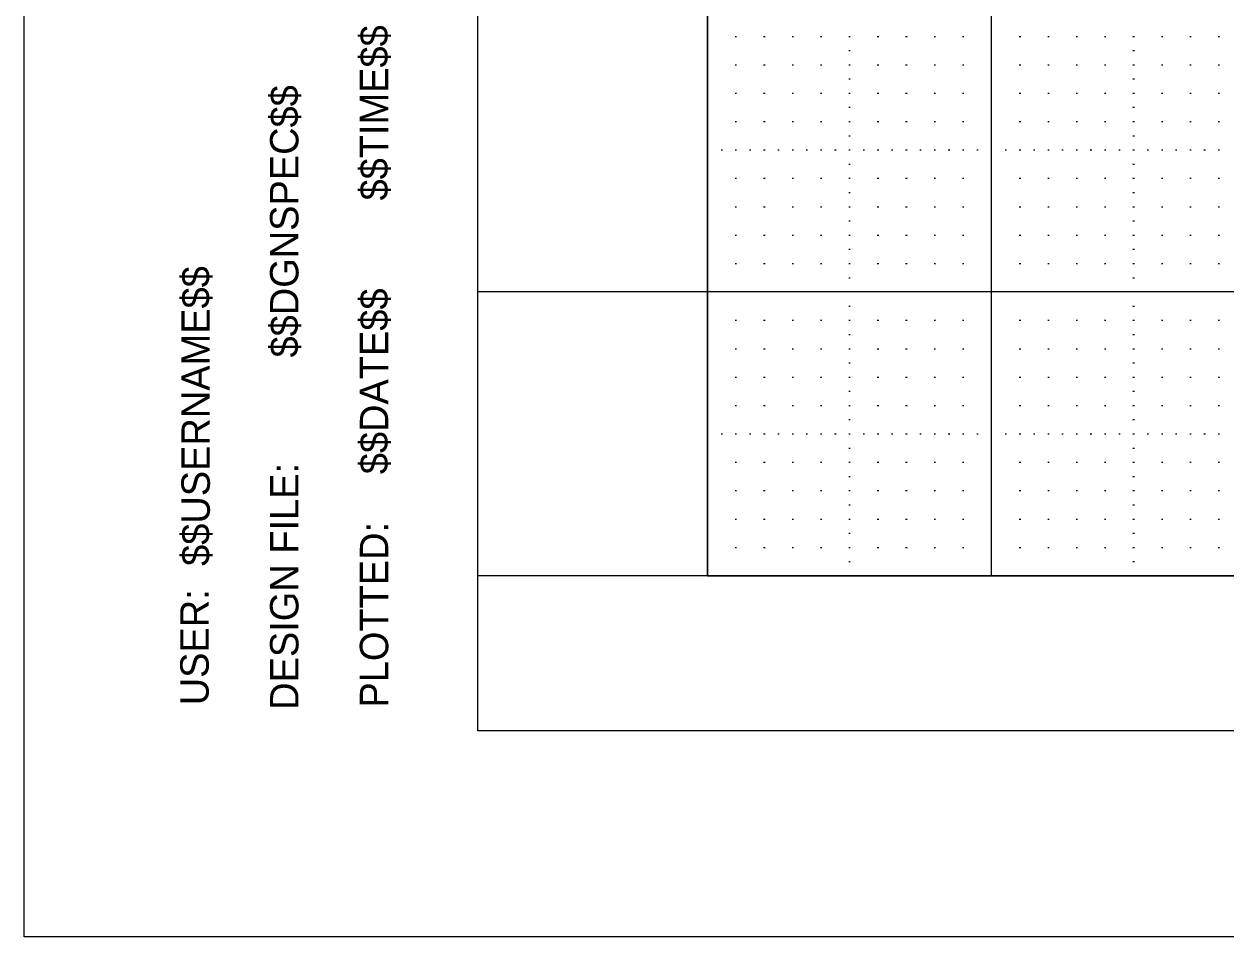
# Model space of a CAD drawing. Extents: x -1.6 to 32.4, y -1.9 to 21.6.
# Drawn here: x -1.598 to 2.633, y -0.727 to 2.488 of the extents above; entities that cross this region are included whole.
import ezdxf

# ---------------------------------------------------------------- set-up
doc = ezdxf.new("R2010")
doc.units = 0
for name, color, linetype in [('Level 1', 7, 'Continuous'), ('Level 4', 7, 'Continuous'), ('Level 5', 7, 'Continuous'), ('Level 61', 7, 'Continuous'), ('Level 63', 7, 'Continuous')]:
    doc.layers.add(name, color=color, linetype=linetype)

msp = doc.modelspace()

# ---------------------------------------------------------------- linework, layer by layer
at = {"layer": 'Level 1'}
for p, q in [((-0.001, -0.001), (-0.001, 20.545)), ((31.617, -0.001), (-0.001, -0.001))]:
    msp.add_line(p, q, dxfattribs=at)
at = {"layer": 'Level 4'}
for p, q in [((0.808, 0.545), (0.808, 20.545)), ((1.808, 0.545), (1.808, 20.545)), ((31.617, 1.545), (-0.001, 1.545)), ((31.617, 0.545), (-0.001, 0.545))]:
    msp.add_line(p, q, dxfattribs=at)
at = {"layer": 'Level 5'}
for p, q in [((0.9055, 2.445), (0.9105, 2.445)), ((1.0055, 2.445), (1.0105, 2.445)), ((1.1055, 2.445), (1.1105, 2.445)), ((1.2055, 2.445), (1.2105, 2.445)), ((1.3055, 2.445), (1.3105, 2.445)), ((1.4055, 2.445), (1.4105, 2.445)), ((1.5055, 2.445), (1.5105, 2.445)), ((1.6055, 2.445), (1.6105, 2.445)), ((1.7055, 2.445), (1.7105, 2.445)), ((1.9055, 2.445), (1.9105, 2.445)), ((2.0055, 2.445), (2.0105, 2.445)), ((2.1055, 2.445), (2.1105, 2.445)), ((2.2055, 2.445), (2.2105, 2.445)), ((2.3055, 2.445), (2.3105, 2.445)), ((2.4055, 2.445), (2.4105, 2.445)), ((2.5055, 2.445), (2.5105, 2.445)), ((2.6055, 2.445), (2.6105, 2.445)), ((1.3055, 2.395), (1.3105, 2.395)), ((2.3055, 2.395), (2.3105, 2.395)), ((0.9055, 2.345), (0.9105, 2.345)), ((1.0055, 2.345), (1.0105, 2.345)), ((1.1055, 2.345), (1.1105, 2.345)), ((1.2055, 2.345), (1.2105, 2.345)), ((1.3055, 2.345), (1.3105, 2.345)), ((1.4055, 2.345), (1.4105, 2.345)), ((1.5055, 2.345), (1.5105, 2.345)), ((1.6055, 2.345), (1.6105, 2.345)), ((1.7055, 2.345), (1.7105, 2.345)), ((1.9055, 2.345), (1.9105, 2.345)), ((2.0055, 2.345), (2.0105, 2.345)), ((2.1055, 2.345), (2.1105, 2.345)), ((2.2055, 2.345), (2.2105, 2.345)), ((2.3055, 2.345), (2.3105, 2.345)), ((2.4055, 2.345), (2.4105, 2.345)), ((2.5055, 2.345), (2.5105, 2.345)), ((2.6055, 2.345), (2.6105, 2.345)), ((1.3055, 2.295), (1.3105, 2.295)), ((2.3055, 2.295), (2.3105, 2.295)), ((0.9055, 2.245), (0.9105, 2.245)), ((1.0055, 2.245), (1.0105, 2.245)), ((1.1055, 2.245), (1.1105, 2.245)), ((1.2055, 2.245), (1.2105, 2.245)), ((1.3055, 2.245), (1.3105, 2.245)), ((1.4055, 2.245), (1.4105, 2.245)), ((1.5055, 2.245), (1.5105, 2.245)), ((1.6055, 2.245), (1.6105, 2.245)), ((1.7055, 2.245), (1.7105, 2.245)), ((1.9055, 2.245), (1.9105, 2.245)), ((2.0055, 2.245), (2.0105, 2.245)), ((2.1055, 2.245), (2.1105, 2.245)), ((2.2055, 2.245), (2.2105, 2.245)), ((2.3055, 2.245), (2.3105, 2.245)), ((2.4055, 2.245), (2.4105, 2.245)), ((2.5055, 2.245), (2.5105, 2.245)), ((2.6055, 2.245), (2.6105, 2.245)), ((1.3055, 2.195), (1.3105, 2.195)), ((2.3055, 2.195), (2.3105, 2.195)), ((0.9055, 2.145), (0.9105, 2.145)), ((1.0055, 2.145), (1.0105, 2.145)), ((1.1055, 2.145), (1.1105, 2.145)), ((1.2055, 2.145), (1.2105, 2.145)), ((1.3055, 2.145), (1.3105, 2.145)), ((1.4055, 2.145), (1.4105, 2.145)), ((1.5055, 2.145), (1.5105, 2.145)), ((1.6055, 2.145), (1.6105, 2.145)), ((1.7055, 2.145), (1.7105, 2.145)), ((1.9055, 2.145), (1.9105, 2.145)), ((2.0055, 2.145), (2.0105, 2.145)), ((2.1055, 2.145), (2.1105, 2.145)), ((2.2055, 2.145), (2.2105, 2.145)), ((2.3055, 2.145), (2.3105, 2.145)), ((2.4055, 2.145), (2.4105, 2.145)), ((2.5055, 2.145), (2.5105, 2.145)), ((2.6055, 2.145), (2.6105, 2.145)), ((1.3055, 2.095), (1.3105, 2.095)), ((2.3055, 2.095), (2.3105, 2.095)), ((0.8555, 2.045), (0.8605, 2.045)), ((0.9055, 2.045), (0.9105, 2.045)), ((0.9555, 2.045), (0.9605, 2.045)), ((1.0055, 2.045), (1.0105, 2.045)), ((1.0555, 2.045), (1.0605, 2.045)), ((1.1055, 2.045), (1.1105, 2.045)), ((1.1555, 2.045), (1.1605, 2.045)), ((1.2055, 2.045), (1.2105, 2.045)), ((1.2555, 2.045), (1.2605, 2.045)), ((1.3055, 2.045), (1.3105, 2.045)), ((1.3555, 2.045), (1.3605, 2.045)), ((1.4055, 2.045), (1.4105, 2.045)), ((1.4555, 2.045), (1.4605, 2.045)), ((1.5055, 2.045), (1.5105, 2.045)), ((1.5555, 2.045), (1.5605, 2.045)), ((1.6055, 2.045), (1.6105, 2.045)), ((1.6555, 2.045), (1.6605, 2.045)), ((1.7055, 2.045), (1.7105, 2.045)), ((1.7555, 2.045), (1.7605, 2.045)), ((1.8555, 2.045), (1.8605, 2.045)), ((1.9055, 2.045), (1.9105, 2.045)), ((1.9555, 2.045), (1.9605, 2.045)), ((2.0055, 2.045), (2.0105, 2.045)), ((2.0555, 2.045), (2.0605, 2.045)), ((2.1055, 2.045), (2.1105, 2.045)), ((2.1555, 2.045), (2.1605, 2.045)), ((2.2055, 2.045), (2.2105, 2.045)), ((2.2555, 2.045), (2.2605, 2.045)), ((2.3055, 2.045), (2.3105, 2.045)), ((2.3555, 2.045), (2.3605, 2.045)), ((2.4055, 2.045), (2.4105, 2.045)), ((2.4555, 2.045), (2.4605, 2.045)), ((2.5055, 2.045), (2.5105, 2.045)), ((2.5555, 2.045), (2.5605, 2.045)), ((2.6055, 2.045), (2.6105, 2.045)), ((1.3055, 1.995), (1.3105, 1.995)), ((2.3055, 1.995), (2.3105, 1.995)), ((0.9055, 1.945), (0.9105, 1.945)), ((1.0055, 1.945), (1.0105, 1.945)), ((1.1055, 1.945), (1.1105, 1.945)), ((1.2055, 1.945), (1.2105, 1.945)), ((1.3055, 1.945), (1.3105, 1.945)), ((1.4055, 1.945), (1.4105, 1.945)), ((1.5055, 1.945), (1.5105, 1.945)), ((1.6055, 1.945), (1.6105, 1.945)), ((1.7055, 1.945), (1.7105, 1.945)), ((1.9055, 1.945), (1.9105, 1.945)), ((2.0055, 1.945), (2.0105, 1.945)), ((2.1055, 1.945), (2.1105, 1.945)), ((2.2055, 1.945), (2.2105, 1.945)), ((2.3055, 1.945), (2.3105, 1.945)), ((2.4055, 1.945), (2.4105, 1.945)), ((2.5055, 1.945), (2.5105, 1.945)), ((2.6055, 1.945), (2.6105, 1.945)), ((1.3055, 1.895), (1.3105, 1.895)), ((2.3055, 1.895), (2.3105, 1.895)), ((0.9055, 1.845), (0.9105, 1.845)), ((1.0055, 1.845), (1.0105, 1.845)), ((1.1055, 1.845), (1.1105, 1.845)), ((1.2055, 1.845), (1.2105, 1.845)), ((1.3055, 1.845), (1.3105, 1.845)), ((1.4055, 1.845), (1.4105, 1.845)), ((1.5055, 1.845), (1.5105, 1.845)), ((1.6055, 1.845), (1.6105, 1.845)), ((1.7055, 1.845), (1.7105, 1.845)), ((1.9055, 1.845), (1.9105, 1.845)), ((2.0055, 1.845), (2.0105, 1.845)), ((2.1055, 1.845), (2.1105, 1.845)), ((2.2055, 1.845), (2.2105, 1.845)), ((2.3055, 1.845), (2.3105, 1.845)), ((2.4055, 1.845), (2.4105, 1.845)), ((2.5055, 1.845), (2.5105, 1.845)), ((2.6055, 1.845), (2.6105, 1.845)), ((1.3055, 1.795), (1.3105, 1.795)), ((2.3055, 1.795), (2.3105, 1.795)), ((0.9055, 1.745), (0.9105, 1.745)), ((1.0055, 1.745), (1.0105, 1.745)), ((1.1055, 1.745), (1.1105, 1.745)), ((1.2055, 1.745), (1.2105, 1.745)), ((1.3055, 1.745), (1.3105, 1.745)), ((1.4055, 1.745), (1.4105, 1.745)), ((1.5055, 1.745), (1.5105, 1.745)), ((1.6055, 1.745), (1.6105, 1.745)), ((1.7055, 1.745), (1.7105, 1.745)), ((1.9055, 1.745), (1.9105, 1.745)), ((2.0055, 1.745), (2.0105, 1.745)), ((2.1055, 1.745), (2.1105, 1.745)), ((2.2055, 1.745), (2.2105, 1.745)), ((2.3055, 1.745), (2.3105, 1.745)), ((2.4055, 1.745), (2.4105, 1.745)), ((2.5055, 1.745), (2.5105, 1.745)), ((2.6055, 1.745), (2.6105, 1.745)), ((1.3055, 1.695), (1.3105, 1.695)), ((2.3055, 1.695), (2.3105, 1.695)), ((0.9055, 1.645), (0.9105, 1.645)), ((1.0055, 1.645), (1.0105, 1.645)), ((1.1055, 1.645), (1.1105, 1.645)), ((1.2055, 1.645), (1.2105, 1.645)), ((1.3055, 1.645), (1.3105, 1.645)), ((1.4055, 1.645), (1.4105, 1.645)), ((1.5055, 1.645), (1.5105, 1.645)), ((1.6055, 1.645), (1.6105, 1.645)), ((1.7055, 1.645), (1.7105, 1.645)), ((1.9055, 1.645), (1.9105, 1.645)), ((2.0055, 1.645), (2.0105, 1.645)), ((2.1055, 1.645), (2.1105, 1.645)), ((2.2055, 1.645), (2.2105, 1.645)), ((2.3055, 1.645), (2.3105, 1.645)), ((2.4055, 1.645), (2.4105, 1.645)), ((2.5055, 1.645), (2.5105, 1.645)), ((2.6055, 1.645), (2.6105, 1.645)), ((1.3055, 1.595), (1.3105, 1.595)), ((2.3055, 1.595), (2.3105, 1.595)), ((1.3055, 1.495), (1.3105, 1.495)), ((2.3055, 1.495), (2.3105, 1.495)), ((0.9055, 1.445), (0.9105, 1.445)), ((1.0055, 1.445), (1.0105, 1.445)), ((1.1055, 1.445), (1.1105, 1.445)), ((1.2055, 1.445), (1.2105, 1.445)), ((1.3055, 1.445), (1.3105, 1.445)), ((1.4055, 1.445), (1.4105, 1.445)), ((1.5055, 1.445), (1.5105, 1.445)), ((1.6055, 1.445), (1.6105, 1.445)), ((1.7055, 1.445), (1.7105, 1.445)), ((1.9055, 1.445), (1.9105, 1.445)), ((2.0055, 1.445), (2.0105, 1.445)), ((2.1055, 1.445), (2.1105, 1.445)), ((2.2055, 1.445), (2.2105, 1.445)), ((2.3055, 1.445), (2.3105, 1.445)), ((2.4055, 1.445), (2.4105, 1.445)), ((2.5055, 1.445), (2.5105, 1.445)), ((2.6055, 1.445), (2.6105, 1.445)), ((1.3055, 1.395), (1.3105, 1.395)), ((2.3055, 1.395), (2.3105, 1.395)), ((0.9055, 1.345), (0.9105, 1.345)), ((1.0055, 1.345), (1.0105, 1.345)), ((1.1055, 1.345), (1.1105, 1.345)), ((1.2055, 1.345), (1.2105, 1.345)), ((1.3055, 1.345), (1.3105, 1.345)), ((1.4055, 1.345), (1.4105, 1.345)), ((1.5055, 1.345), (1.5105, 1.345)), ((1.6055, 1.345), (1.6105, 1.345)), ((1.7055, 1.345), (1.7105, 1.345)), ((1.9055, 1.345), (1.9105, 1.345)), ((2.0055, 1.345), (2.0105, 1.345)), ((2.1055, 1.345), (2.1105, 1.345)), ((2.2055, 1.345), (2.2105, 1.345)), ((2.3055, 1.345), (2.3105, 1.345)), ((2.4055, 1.345), (2.4105, 1.345)), ((2.5055, 1.345), (2.5105, 1.345)), ((2.6055, 1.345), (2.6105, 1.345)), ((1.3055, 1.295), (1.3105, 1.295)), ((2.3055, 1.295), (2.3105, 1.295)), ((0.9055, 1.245), (0.9105, 1.245)), ((1.0055, 1.245), (1.0105, 1.245)), ((1.1055, 1.245), (1.1105, 1.245)), ((1.2055, 1.245), (1.2105, 1.245)), ((1.3055, 1.245), (1.3105, 1.245)), ((1.4055, 1.245), (1.4105, 1.245)), ((1.5055, 1.245), (1.5105, 1.245)), ((1.6055, 1.245), (1.6105, 1.245)), ((1.7055, 1.245), (1.7105, 1.245)), ((1.9055, 1.245), (1.9105, 1.245)), ((2.0055, 1.245), (2.0105, 1.245)), ((2.1055, 1.245), (2.1105, 1.245)), ((2.2055, 1.245), (2.2105, 1.245)), ((2.3055, 1.245), (2.3105, 1.245)), ((2.4055, 1.245), (2.4105, 1.245)), ((2.5055, 1.245), (2.5105, 1.245)), ((2.6055, 1.245), (2.6105, 1.245)), ((1.3055, 1.195), (1.3105, 1.195)), ((2.3055, 1.195), (2.3105, 1.195)), ((0.9055, 1.145), (0.9105, 1.145)), ((1.0055, 1.145), (1.0105, 1.145)), ((1.1055, 1.145), (1.1105, 1.145)), ((1.2055, 1.145), (1.2105, 1.145)), ((1.3055, 1.145), (1.3105, 1.145)), ((1.4055, 1.145), (1.4105, 1.145)), ((1.5055, 1.145), (1.5105, 1.145)), ((1.6055, 1.145), (1.6105, 1.145)), ((1.7055, 1.145), (1.7105, 1.145)), ((1.9055, 1.145), (1.9105, 1.145)), ((2.0055, 1.145), (2.0105, 1.145)), ((2.1055, 1.145), (2.1105, 1.145)), ((2.2055, 1.145), (2.2105, 1.145)), ((2.3055, 1.145), (2.3105, 1.145)), ((2.4055, 1.145), (2.4105, 1.145)), ((2.5055, 1.145), (2.5105, 1.145)), ((2.6055, 1.145), (2.6105, 1.145)), ((1.3055, 1.095), (1.3105, 1.095)), ((2.3055, 1.095), (2.3105, 1.095)), ((0.8555, 1.045), (0.8605, 1.045)), ((0.9055, 1.045), (0.9105, 1.045)), ((0.9555, 1.045), (0.9605, 1.045)), ((1.0055, 1.045), (1.0105, 1.045)), ((1.0555, 1.045), (1.0605, 1.045)), ((1.1055, 1.045), (1.1105, 1.045)), ((1.1555, 1.045), (1.1605, 1.045)), ((1.2055, 1.045), (1.2105, 1.045)), ((1.2555, 1.045), (1.2605, 1.045)), ((1.3055, 1.045), (1.3105, 1.045)), ((1.3555, 1.045), (1.3605, 1.045)), ((1.4055, 1.045), (1.4105, 1.045)), ((1.4555, 1.045), (1.4605, 1.045)), ((1.5055, 1.045), (1.5105, 1.045)), ((1.5555, 1.045), (1.5605, 1.045)), ((1.6055, 1.045), (1.6105, 1.045)), ((1.6555, 1.045), (1.6605, 1.045)), ((1.7055, 1.045), (1.7105, 1.045)), ((1.7555, 1.045), (1.7605, 1.045)), ((1.8555, 1.045), (1.8605, 1.045)), ((1.9055, 1.045), (1.9105, 1.045)), ((1.9555, 1.045), (1.9605, 1.045)), ((2.0055, 1.045), (2.0105, 1.045)), ((2.0555, 1.045), (2.0605, 1.045)), ((2.1055, 1.045), (2.1105, 1.045)), ((2.1555, 1.045), (2.1605, 1.045)), ((2.2055, 1.045), (2.2105, 1.045)), ((2.2555, 1.045), (2.2605, 1.045)), ((2.3055, 1.045), (2.3105, 1.045)), ((2.3555, 1.045), (2.3605, 1.045)), ((2.4055, 1.045), (2.4105, 1.045)), ((2.4555, 1.045), (2.4605, 1.045)), ((2.5055, 1.045), (2.5105, 1.045)), ((2.5555, 1.045), (2.5605, 1.045)), ((2.6055, 1.045), (2.6105, 1.045)), ((1.3055, 0.995), (1.3105, 0.995)), ((2.3055, 0.995), (2.3105, 0.995)), ((0.9055, 0.945), (0.9105, 0.945)), ((1.0055, 0.945), (1.0105, 0.945)), ((1.1055, 0.945), (1.1105, 0.945)), ((1.2055, 0.945), (1.2105, 0.945)), ((1.3055, 0.945), (1.3105, 0.945)), ((1.4055, 0.945), (1.4105, 0.945)), ((1.5055, 0.945), (1.5105, 0.945)), ((1.6055, 0.945), (1.6105, 0.945)), ((1.7055, 0.945), (1.7105, 0.945)), ((1.9055, 0.945), (1.9105, 0.945)), ((2.0055, 0.945), (2.0105, 0.945)), ((2.1055, 0.945), (2.1105, 0.945)), ((2.2055, 0.945), (2.2105, 0.945)), ((2.3055, 0.945), (2.3105, 0.945)), ((2.4055, 0.945), (2.4105, 0.945)), ((2.5055, 0.945), (2.5105, 0.945)), ((2.6055, 0.945), (2.6105, 0.945)), ((1.3055, 0.895), (1.3105, 0.895)), ((2.3055, 0.895), (2.3105, 0.895)), ((0.9055, 0.845), (0.9105, 0.845)), ((1.0055, 0.845), (1.0105, 0.845)), ((1.1055, 0.845), (1.1105, 0.845)), ((1.2055, 0.845), (1.2105, 0.845)), ((1.3055, 0.845), (1.3105, 0.845)), ((1.4055, 0.845), (1.4105, 0.845)), ((1.5055, 0.845), (1.5105, 0.845)), ((1.6055, 0.845), (1.6105, 0.845)), ((1.7055, 0.845), (1.7105, 0.845)), ((1.9055, 0.845), (1.9105, 0.845)), ((2.0055, 0.845), (2.0105, 0.845)), ((2.1055, 0.845), (2.1105, 0.845)), ((2.2055, 0.845), (2.2105, 0.845)), ((2.3055, 0.845), (2.3105, 0.845)), ((2.4055, 0.845), (2.4105, 0.845)), ((2.5055, 0.845), (2.5105, 0.845)), ((2.6055, 0.845), (2.6105, 0.845)), ((1.3055, 0.795), (1.3105, 0.795)), ((2.3055, 0.795), (2.3105, 0.795)), ((0.9055, 0.745), (0.9105, 0.745)), ((1.0055, 0.745), (1.0105, 0.745)), ((1.1055, 0.745), (1.1105, 0.745)), ((1.2055, 0.745), (1.2105, 0.745)), ((1.3055, 0.745), (1.3105, 0.745)), ((1.4055, 0.745), (1.4105, 0.745)), ((1.5055, 0.745), (1.5105, 0.745)), ((1.6055, 0.745), (1.6105, 0.745)), ((1.7055, 0.745), (1.7105, 0.745)), ((1.9055, 0.745), (1.9105, 0.745)), ((2.0055, 0.745), (2.0105, 0.745)), ((2.1055, 0.745), (2.1105, 0.745)), ((2.2055, 0.745), (2.2105, 0.745)), ((2.3055, 0.745), (2.3105, 0.745)), ((2.4055, 0.745), (2.4105, 0.745)), ((2.5055, 0.745), (2.5105, 0.745)), ((2.6055, 0.745), (2.6105, 0.745)), ((1.3055, 0.695), (1.3105, 0.695)), ((2.3055, 0.695), (2.3105, 0.695)), ((0.9055, 0.645), (0.9105, 0.645)), ((1.0055, 0.645), (1.0105, 0.645)), ((1.1055, 0.645), (1.1105, 0.645)), ((1.2055, 0.645), (1.2105, 0.645)), ((1.3055, 0.645), (1.3105, 0.645)), ((1.4055, 0.645), (1.4105, 0.645)), ((1.5055, 0.645), (1.5105, 0.645)), ((1.6055, 0.645), (1.6105, 0.645)), ((1.7055, 0.645), (1.7105, 0.645)), ((1.9055, 0.645), (1.9105, 0.645)), ((2.0055, 0.645), (2.0105, 0.645)), ((2.1055, 0.645), (2.1105, 0.645)), ((2.2055, 0.645), (2.2105, 0.645)), ((2.3055, 0.645), (2.3105, 0.645)), ((2.4055, 0.645), (2.4105, 0.645)), ((2.5055, 0.645), (2.5105, 0.645)), ((2.6055, 0.645), (2.6105, 0.645)), ((1.3055, 0.595), (1.3105, 0.595)), ((2.3055, 0.595), (2.3105, 0.595))]:
    msp.add_line(p, q, dxfattribs=at)
at = {"layer": 'Level 61'}
msp.add_lwpolyline([(0.808, 0.545), (30.808, 0.545), (30.8079, 19.7222), (26.3984, 19.7217), (26.3984, 19.7217), (26.3984, 19.7217), (26.3984, 19.7217), (26.3984, 19.7217), (26.3984, 20.545), (26.3984, 20.545), (26.3984, 20.545), (0.808, 20.545)], close=True, dxfattribs=at)
at = {"layer": 'Level 63'}
msp.add_lwpolyline([(-1.598, 21.273), (32.402, 21.273), (32.402, -0.727), (-1.598, -0.727)], close=True, dxfattribs=at)

# ---------------------------------------------------------------- texts
at = {"layer": 'Level 1'}
for s, height, p in [('$$TIME$$', 0.1, (-0.316, 1.867)), ('$$DGNSPEC$$', 0.100002, (-0.632, 1.314)), ('$$USERNAME$$', 0.100002, (-0.944, 0.58)), ('$$DATE$$', 0.1, (-0.316, 0.903)), ('DESIGN FILE:', 0.100002, (-0.632, 0.073)), ('PLOTTED:', 0.1, (-0.316, 0.081)), ('USER:', 0.1, (-0.948, 0.089))]:
    msp.add_text(s, height=height, rotation=90, dxfattribs=at).set_placement(p)

doc.saveas('drawing.dxf')
